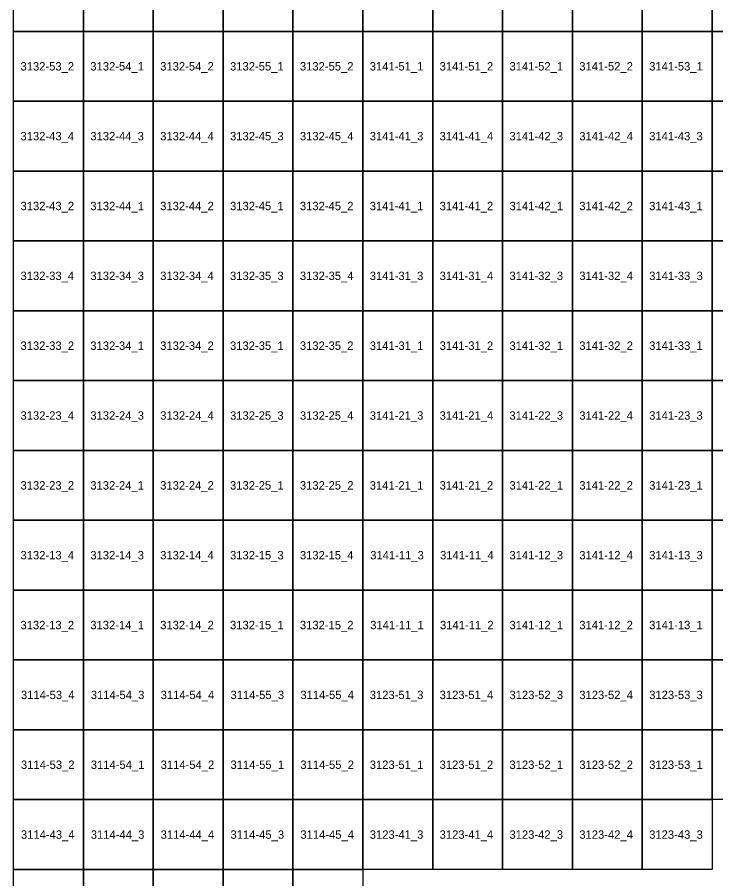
# Model space of a CAD drawing. Extents: x 312500 to 765000, y 172500 to 440000.
# Drawn here: x 337632 to 362632, y 242168 to 273007 of the extents above; entities that cross this region are included whole.
import ezdxf

# ---------------------------------------------------------------- set-up
doc = ezdxf.new("R2010")
doc.units = 0
doc.layers.add('Topo5_ramis_TKS2025', color=7, linetype='Continuous')
doc.layers.add('Topo5_ramis_TKS2025_Nr', color=7, linetype='Continuous')

msp = doc.modelspace()

# ---------------------------------------------------------------- linework, layer by layer
at = {"layer": 'Topo5_ramis_TKS2025'}
for points in [[(337500, 272500), (337500, 275000), (340000, 275000), (340000, 272500), (337500, 272500)], [(340000, 272500), (340000, 275000), (342500, 275000), (342500, 272500), (340000, 272500)], [(342500, 272500), (342500, 275000), (345000, 275000), (345000, 272500), (342500, 272500)], [(345000, 272500), (345000, 275000), (347500, 275000), (347500, 272500), (345000, 272500)], [(347500, 272500), (347500, 275000), (350000, 275000), (350000, 272500), (347500, 272500)], [(350000, 272500), (350000, 275000), (352500, 275000), (352500, 272500), (350000, 272500)], [(352500, 272500), (352500, 275000), (355000, 275000), (355000, 272500), (352500, 272500)], [(355000, 272500), (355000, 275000), (357500, 275000), (357500, 272500), (355000, 272500)], [(357500, 272500), (357500, 275000), (360000, 275000), (360000, 272500), (357500, 272500)], [(360000, 272500), (360000, 275000), (362500, 275000), (362500, 272500), (360000, 272500)], [(362500, 272500), (362500, 275000), (365000, 275000), (365000, 272500), (362500, 272500)], [(337500, 270000), (337500, 272500), (340000, 272500), (340000, 270000), (337500, 270000)], [(340000, 270000), (340000, 272500), (342500, 272500), (342500, 270000), (340000, 270000)], [(342500, 270000), (342500, 272500), (345000, 272500), (345000, 270000), (342500, 270000)], [(345000, 270000), (345000, 272500), (347500, 272500), (347500, 270000), (345000, 270000)], [(347500, 270000), (347500, 272500), (350000, 272500), (350000, 270000), (347500, 270000)], [(350000, 270000), (350000, 272500), (352500, 272500), (352500, 270000), (350000, 270000)], [(352500, 270000), (352500, 272500), (355000, 272500), (355000, 270000), (352500, 270000)], [(355000, 270000), (355000, 272500), (357500, 272500), (357500, 270000), (355000, 270000)], [(357500, 270000), (357500, 272500), (360000, 272500), (360000, 270000), (357500, 270000)], [(360000, 270000), (360000, 272500), (362500, 272500), (362500, 270000), (360000, 270000)], [(362500, 270000), (362500, 272500), (365000, 272500), (365000, 270000), (362500, 270000)], [(337500, 267500), (337500, 270000), (340000, 270000), (340000, 267500), (337500, 267500)], [(340000, 267500), (340000, 270000), (342500, 270000), (342500, 267500), (340000, 267500)], [(342500, 267500), (342500, 270000), (345000, 270000), (345000, 267500), (342500, 267500)], [(345000, 267500), (345000, 270000), (347500, 270000), (347500, 267500), (345000, 267500)], [(347500, 267500), (347500, 270000), (350000, 270000), (350000, 267500), (347500, 267500)], [(350000, 267500), (350000, 270000), (352500, 270000), (352500, 267500), (350000, 267500)], [(352500, 267500), (352500, 270000), (355000, 270000), (355000, 267500), (352500, 267500)], [(355000, 267500), (355000, 270000), (357500, 270000), (357500, 267500), (355000, 267500)], [(357500, 267500), (357500, 270000), (360000, 270000), (360000, 267500), (357500, 267500)], [(360000, 267500), (360000, 270000), (362500, 270000), (362500, 267500), (360000, 267500)], [(362500, 267500), (362500, 270000), (365000, 270000), (365000, 267500), (362500, 267500)], [(337500, 265000), (337500, 267500), (340000, 267500), (340000, 265000), (337500, 265000)], [(340000, 265000), (340000, 267500), (342500, 267500), (342500, 265000), (340000, 265000)], [(342500, 265000), (342500, 267500), (345000, 267500), (345000, 265000), (342500, 265000)], [(345000, 265000), (345000, 267500), (347500, 267500), (347500, 265000), (345000, 265000)], [(347500, 265000), (347500, 267500), (350000, 267500), (350000, 265000), (347500, 265000)], [(350000, 265000), (350000, 267500), (352500, 267500), (352500, 265000), (350000, 265000)], [(352500, 265000), (352500, 267500), (355000, 267500), (355000, 265000), (352500, 265000)], [(355000, 265000), (355000, 267500), (357500, 267500), (357500, 265000), (355000, 265000)], [(357500, 265000), (357500, 267500), (360000, 267500), (360000, 265000), (357500, 265000)], [(360000, 265000), (360000, 267500), (362500, 267500), (362500, 265000), (360000, 265000)], [(362500, 265000), (362500, 267500), (365000, 267500), (365000, 265000), (362500, 265000)], [(337500, 262500), (337500, 265000), (340000, 265000), (340000, 262500), (337500, 262500)], [(340000, 262500), (340000, 265000), (342500, 265000), (342500, 262500), (340000, 262500)], [(342500, 262500), (342500, 265000), (345000, 265000), (345000, 262500), (342500, 262500)], [(345000, 262500), (345000, 265000), (347500, 265000), (347500, 262500), (345000, 262500)], [(347500, 262500), (347500, 265000), (350000, 265000), (350000, 262500), (347500, 262500)], [(350000, 262500), (350000, 265000), (352500, 265000), (352500, 262500), (350000, 262500)], [(352500, 262500), (352500, 265000), (355000, 265000), (355000, 262500), (352500, 262500)], [(355000, 262500), (355000, 265000), (357500, 265000), (357500, 262500), (355000, 262500)], [(357500, 262500), (357500, 265000), (360000, 265000), (360000, 262500), (357500, 262500)], [(360000, 262500), (360000, 265000), (362500, 265000), (362500, 262500), (360000, 262500)], [(362500, 262500), (362500, 265000), (365000, 265000), (365000, 262500), (362500, 262500)], [(337500, 260000), (337500, 262500), (340000, 262500), (340000, 260000), (337500, 260000)], [(340000, 260000), (340000, 262500), (342500, 262500), (342500, 260000), (340000, 260000)], [(342500, 260000), (342500, 262500), (345000, 262500), (345000, 260000), (342500, 260000)], [(345000, 260000), (345000, 262500), (347500, 262500), (347500, 260000), (345000, 260000)], [(347500, 260000), (347500, 262500), (350000, 262500), (350000, 260000), (347500, 260000)], [(350000, 260000), (350000, 262500), (352500, 262500), (352500, 260000), (350000, 260000)], [(352500, 260000), (352500, 262500), (355000, 262500), (355000, 260000), (352500, 260000)], [(355000, 260000), (355000, 262500), (357500, 262500), (357500, 260000), (355000, 260000)], [(357500, 260000), (357500, 262500), (360000, 262500), (360000, 260000), (357500, 260000)], [(360000, 260000), (360000, 262500), (362500, 262500), (362500, 260000), (360000, 260000)], [(362500, 260000), (362500, 262500), (365000, 262500), (365000, 260000), (362500, 260000)], [(337500, 257500), (337500, 260000), (340000, 260000), (340000, 257500), (337500, 257500)], [(340000, 257500), (340000, 260000), (342500, 260000), (342500, 257500), (340000, 257500)], [(342500, 257500), (342500, 260000), (345000, 260000), (345000, 257500), (342500, 257500)], [(345000, 257500), (345000, 260000), (347500, 260000), (347500, 257500), (345000, 257500)], [(347500, 257500), (347500, 260000), (350000, 260000), (350000, 257500), (347500, 257500)], [(350000, 257500), (350000, 260000), (352500, 260000), (352500, 257500), (350000, 257500)], [(352500, 257500), (352500, 260000), (355000, 260000), (355000, 257500), (352500, 257500)], [(355000, 257500), (355000, 260000), (357500, 260000), (357500, 257500), (355000, 257500)], [(357500, 257500), (357500, 260000), (360000, 260000), (360000, 257500), (357500, 257500)], [(360000, 257500), (360000, 260000), (362500, 260000), (362500, 257500), (360000, 257500)], [(362500, 257500), (362500, 260000), (365000, 260000), (365000, 257500), (362500, 257500)], [(337500, 255000), (337500, 257500), (340000, 257500), (340000, 255000), (337500, 255000)], [(340000, 255000), (340000, 257500), (342500, 257500), (342500, 255000), (340000, 255000)], [(342500, 255000), (342500, 257500), (345000, 257500), (345000, 255000), (342500, 255000)], [(345000, 255000), (345000, 257500), (347500, 257500), (347500, 255000), (345000, 255000)], [(347500, 255000), (347500, 257500), (350000, 257500), (350000, 255000), (347500, 255000)], [(350000, 255000), (350000, 257500), (352500, 257500), (352500, 255000), (350000, 255000)], [(352500, 255000), (352500, 257500), (355000, 257500), (355000, 255000), (352500, 255000)], [(355000, 255000), (355000, 257500), (357500, 257500), (357500, 255000), (355000, 255000)], [(357500, 255000), (357500, 257500), (360000, 257500), (360000, 255000), (357500, 255000)], [(360000, 255000), (360000, 257500), (362500, 257500), (362500, 255000), (360000, 255000)], [(362500, 255000), (362500, 257500), (365000, 257500), (365000, 255000), (362500, 255000)], [(337500, 252500), (337500, 255000), (340000, 255000), (340000, 252500), (337500, 252500)], [(340000, 252500), (340000, 255000), (342500, 255000), (342500, 252500), (340000, 252500)], [(342500, 252500), (342500, 255000), (345000, 255000), (345000, 252500), (342500, 252500)], [(345000, 252500), (345000, 255000), (347500, 255000), (347500, 252500), (345000, 252500)], [(347500, 252500), (347500, 255000), (350000, 255000), (350000, 252500), (347500, 252500)], [(350000, 252500), (350000, 255000), (352500, 255000), (352500, 252500), (350000, 252500)], [(352500, 252500), (352500, 255000), (355000, 255000), (355000, 252500), (352500, 252500)], [(355000, 252500), (355000, 255000), (357500, 255000), (357500, 252500), (355000, 252500)], [(357500, 252500), (357500, 255000), (360000, 255000), (360000, 252500), (357500, 252500)], [(360000, 252500), (360000, 255000), (362500, 255000), (362500, 252500), (360000, 252500)], [(362500, 252500), (362500, 255000), (365000, 255000), (365000, 252500), (362500, 252500)], [(337500, 250000), (337500, 252500), (340000, 252500), (340000, 250000), (337500, 250000)], [(340000, 250000), (340000, 252500), (342500, 252500), (342500, 250000), (340000, 250000)], [(342500, 250000), (342500, 252500), (345000, 252500), (345000, 250000), (342500, 250000)], [(345000, 250000), (345000, 252500), (347500, 252500), (347500, 250000), (345000, 250000)], [(347500, 250000), (347500, 252500), (350000, 252500), (350000, 250000), (347500, 250000)], [(350000, 250000), (350000, 252500), (352500, 252500), (352500, 250000), (350000, 250000)], [(352500, 250000), (352500, 252500), (355000, 252500), (355000, 250000), (352500, 250000)], [(355000, 250000), (355000, 252500), (357500, 252500), (357500, 250000), (355000, 250000)], [(357500, 250000), (357500, 252500), (360000, 252500), (360000, 250000), (357500, 250000)], [(360000, 250000), (360000, 252500), (362500, 252500), (362500, 250000), (360000, 250000)], [(362500, 250000), (362500, 252500), (365000, 252500), (365000, 250000), (362500, 250000)], [(337500, 247500), (337500, 250000), (340000, 250000), (340000, 247500), (337500, 247500)], [(340000, 247500), (340000, 250000), (342500, 250000), (342500, 247500), (340000, 247500)], [(342500, 247500), (342500, 250000), (345000, 250000), (345000, 247500), (342500, 247500)], [(345000, 247500), (345000, 250000), (347500, 250000), (347500, 247500), (345000, 247500)], [(347500, 247500), (347500, 250000), (350000, 250000), (350000, 247500), (347500, 247500)], [(350000, 247500), (350000, 250000), (352500, 250000), (352500, 247500), (350000, 247500)], [(352500, 247500), (352500, 250000), (355000, 250000), (355000, 247500), (352500, 247500)], [(355000, 247500), (355000, 250000), (357500, 250000), (357500, 247500), (355000, 247500)], [(357500, 247500), (357500, 250000), (360000, 250000), (360000, 247500), (357500, 247500)], [(360000, 247500), (360000, 250000), (362500, 250000), (362500, 247500), (360000, 247500)], [(362500, 247500), (362500, 250000), (365000, 250000), (365000, 247500), (362500, 247500)], [(337500, 245000), (337500, 247500), (340000, 247500), (340000, 245000), (337500, 245000)], [(340000, 245000), (340000, 247500), (342500, 247500), (342500, 245000), (340000, 245000)], [(342500, 245000), (342500, 247500), (345000, 247500), (345000, 245000), (342500, 245000)], [(345000, 245000), (345000, 247500), (347500, 247500), (347500, 245000), (345000, 245000)], [(347500, 245000), (347500, 247500), (350000, 247500), (350000, 245000), (347500, 245000)], [(350000, 245000), (350000, 247500), (352500, 247500), (352500, 245000), (350000, 245000)], [(352500, 245000), (352500, 247500), (355000, 247500), (355000, 245000), (352500, 245000)], [(355000, 245000), (355000, 247500), (357500, 247500), (357500, 245000), (355000, 245000)], [(357500, 245000), (357500, 247500), (360000, 247500), (360000, 245000), (357500, 245000)], [(360000, 245000), (360000, 247500), (362500, 247500), (362500, 245000), (360000, 245000)], [(362500, 245000), (362500, 247500), (365000, 247500), (365000, 245000), (362500, 245000)], [(337500, 242500), (337500, 245000), (340000, 245000), (340000, 242500), (337500, 242500)], [(340000, 242500), (340000, 245000), (342500, 245000), (342500, 242500), (340000, 242500)], [(342500, 242500), (342500, 245000), (345000, 245000), (345000, 242500), (342500, 242500)], [(345000, 242500), (345000, 245000), (347500, 245000), (347500, 242500), (345000, 242500)], [(347500, 242500), (347500, 245000), (350000, 245000), (350000, 242500), (347500, 242500)], [(350000, 242500), (350000, 245000), (352500, 245000), (352500, 242500), (350000, 242500)], [(352500, 242500), (352500, 245000), (355000, 245000), (355000, 242500), (352500, 242500)], [(355000, 242500), (355000, 245000), (357500, 245000), (357500, 242500), (355000, 242500)], [(357500, 242500), (357500, 245000), (360000, 245000), (360000, 242500), (357500, 242500)], [(360000, 242500), (360000, 245000), (362500, 245000), (362500, 242500), (360000, 242500)], [(337500, 240000), (337500, 242500), (340000, 242500), (340000, 240000), (337500, 240000)], [(340000, 240000), (340000, 242500), (342500, 242500), (342500, 240000), (340000, 240000)], [(342500, 240000), (342500, 242500), (345000, 242500), (345000, 240000), (342500, 240000)], [(345000, 240000), (345000, 242500), (347500, 242500), (347500, 240000), (345000, 240000)], [(347500, 240000), (347500, 242500), (350000, 242500), (350000, 240000), (347500, 240000)]]:
    msp.add_lwpolyline(points, dxfattribs=at)

# ---------------------------------------------------------------- texts
at = {"layer": 'Topo5_ramis_TKS2025_Nr'}
for s, p in [('3132-53_2', (337748, 271100)), ('3132-54_1', (340248, 271100)), ('3132-54_2', (342748, 271100)), ('3132-55_1', (345248, 271100)), ('3132-55_2', (347748, 271100)), ('3141-51_1', (350248, 271100)), ('3141-51_2', (352748, 271100)), ('3141-52_1', (355248, 271100)), ('3141-52_2', (357748, 271100)), ('3141-53_1', (360248, 271100)), ('3132-43_4', (337748, 268600)), ('3132-44_3', (340248, 268600)), ('3132-44_4', (342748, 268600)), ('3132-45_3', (345248, 268600)), ('3132-45_4', (347748, 268600)), ('3141-41_3', (350248, 268600)), ('3141-41_4', (352748, 268600)), ('3141-42_3', (355248, 268600)), ('3141-42_4', (357748, 268600)), ('3141-43_3', (360248, 268600)), ('3132-43_2', (337748, 266100)), ('3132-44_1', (340248, 266100)), ('3132-44_2', (342748, 266100)), ('3132-45_1', (345248, 266100)), ('3132-45_2', (347748, 266100)), ('3141-41_1', (350248, 266100)), ('3141-41_2', (352748, 266100)), ('3141-42_1', (355248, 266100)), ('3141-42_2', (357748, 266100)), ('3141-43_1', (360248, 266100)), ('3132-33_4', (337748, 263600)), ('3132-34_3', (340248, 263600)), ('3132-34_4', (342748, 263600)), ('3132-35_3', (345248, 263600)), ('3132-35_4', (347748, 263600)), ('3141-31_3', (350248, 263600)), ('3141-31_4', (352748, 263600)), ('3141-32_3', (355248, 263600)), ('3141-32_4', (357748, 263600)), ('3141-33_3', (360248, 263600)), ('3132-33_2', (337748, 261100)), ('3132-34_1', (340248, 261100)), ('3132-34_2', (342748, 261100)), ('3132-35_1', (345248, 261100)), ('3132-35_2', (347748, 261100)), ('3141-31_1', (350248, 261100)), ('3141-31_2', (352748, 261100)), ('3141-32_1', (355248, 261100)), ('3141-32_2', (357748, 261100)), ('3141-33_1', (360248, 261100)), ('3132-23_4', (337748, 258600)), ('3132-24_3', (340248, 258600)), ('3132-24_4', (342748, 258600)), ('3132-25_3', (345248, 258600)), ('3132-25_4', (347748, 258600)), ('3141-21_3', (350248, 258600)), ('3141-21_4', (352748, 258600)), ('3141-22_3', (355248, 258600)), ('3141-22_4', (357748, 258600)), ('3141-23_3', (360248, 258600)), ('3132-23_2', (337748, 256100)), ('3132-24_1', (340248, 256100)), ('3132-24_2', (342748, 256100)), ('3132-25_1', (345248, 256100)), ('3132-25_2', (347748, 256100)), ('3141-21_1', (350248, 256100)), ('3141-21_2', (352748, 256100)), ('3141-22_1', (355248, 256100)), ('3141-22_2', (357748, 256100)), ('3141-23_1', (360248, 256100)), ('3132-13_4', (337748, 253600)), ('3132-14_3', (340248, 253600)), ('3132-14_4', (342748, 253600)), ('3132-15_3', (345248, 253600)), ('3132-15_4', (347748, 253600)), ('3141-11_3', (350264, 253600)), ('3141-11_4', (352764, 253600)), ('3141-12_3', (355248, 253600)), ('3141-12_4', (357748, 253600)), ('3141-13_3', (360248, 253600)), ('3132-13_2', (337748, 251100)), ('3132-14_1', (340248, 251100)), ('3132-14_2', (342748, 251100)), ('3132-15_1', (345248, 251100)), ('3132-15_2', (347748, 251100)), ('3141-11_1', (350264, 251100)), ('3141-11_2', (352764, 251100)), ('3141-12_1', (355248, 251100)), ('3141-12_2', (357748, 251100)), ('3141-13_1', (360248, 251100)), ('3114-53_4', (337764, 248600)), ('3114-54_3', (340264, 248600)), ('3114-54_4', (342764, 248600)), ('3114-55_3', (345264, 248600)), ('3114-55_4', (347764, 248600)), ('3123-51_3', (350248, 248600)), ('3123-51_4', (352748, 248600)), ('3123-52_3', (355248, 248600)), ('3123-52_4', (357748, 248600)), ('3123-53_3', (360248, 248600)), ('3114-53_2', (337764, 246100)), ('3114-54_1', (340264, 246100)), ('3114-54_2', (342764, 246100)), ('3114-55_1', (345264, 246100)), ('3114-55_2', (347764, 246100)), ('3123-51_1', (350248, 246100)), ('3123-51_2', (352748, 246100)), ('3123-52_1', (355248, 246100)), ('3123-52_2', (357748, 246100)), ('3123-53_1', (360248, 246100)), ('3114-43_4', (337764, 243600)), ('3114-44_3', (340264, 243600)), ('3114-44_4', (342764, 243600)), ('3114-45_3', (345264, 243600)), ('3114-45_4', (347764, 243600)), ('3123-41_3', (350248, 243600)), ('3123-41_4', (352748, 243600)), ('3123-42_3', (355248, 243600)), ('3123-42_4', (357748, 243600)), ('3123-43_3', (360248, 243600))]:
    msp.add_text(s, height=300, dxfattribs=at).set_placement(p)

doc.saveas('drawing.dxf')
